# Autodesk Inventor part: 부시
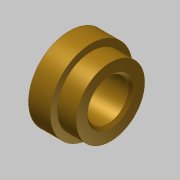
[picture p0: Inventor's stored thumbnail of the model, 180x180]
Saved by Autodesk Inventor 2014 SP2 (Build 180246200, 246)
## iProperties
Created: 2016-05
Part Number: 부시
Document SubType Name: Modeling
Designer: mduedu
Density: 7.86 g/cm^3
Material: 강철, 연강
Appearance: 황동 - 새틴
Author: mduedu
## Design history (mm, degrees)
sketch "스케치1"
  geometry: L1 (0, 0)-(15, 0); L2 (0, 7.5)-(15, 7.5); L3 (15, 7.5)-(15, 12.5); L4 (15, 12.5)-(8, 12.5); L5 (8, 12.5)-(8, 15); L6 (8, 15)-(0, 15); L7 (0, 15)-(0, 7.5)
  constraints: 14 end point, 4 parallel, 2 vertical alignment, 1 horizontal, 1 perpendicular, 1 vertical
  dimensions: "d0" = 15 distance of L1.start L1.end; "d1" = 15 diameter of L2 L1; "d2" = 25 diameter of L4 L1; "d3" = 8 distance of L5.end L6.end; "d4" = 30 diameter of L6 L1
revolve "회전1" sketch "스케치1" stored, may be unused: angle "d5" = 90 deg
chamfer "모따기1" distance "d6" = 1; stored, may be unused: second distance "d7" = 2, angle "d8" = 45 deg
node "솔리드1"
